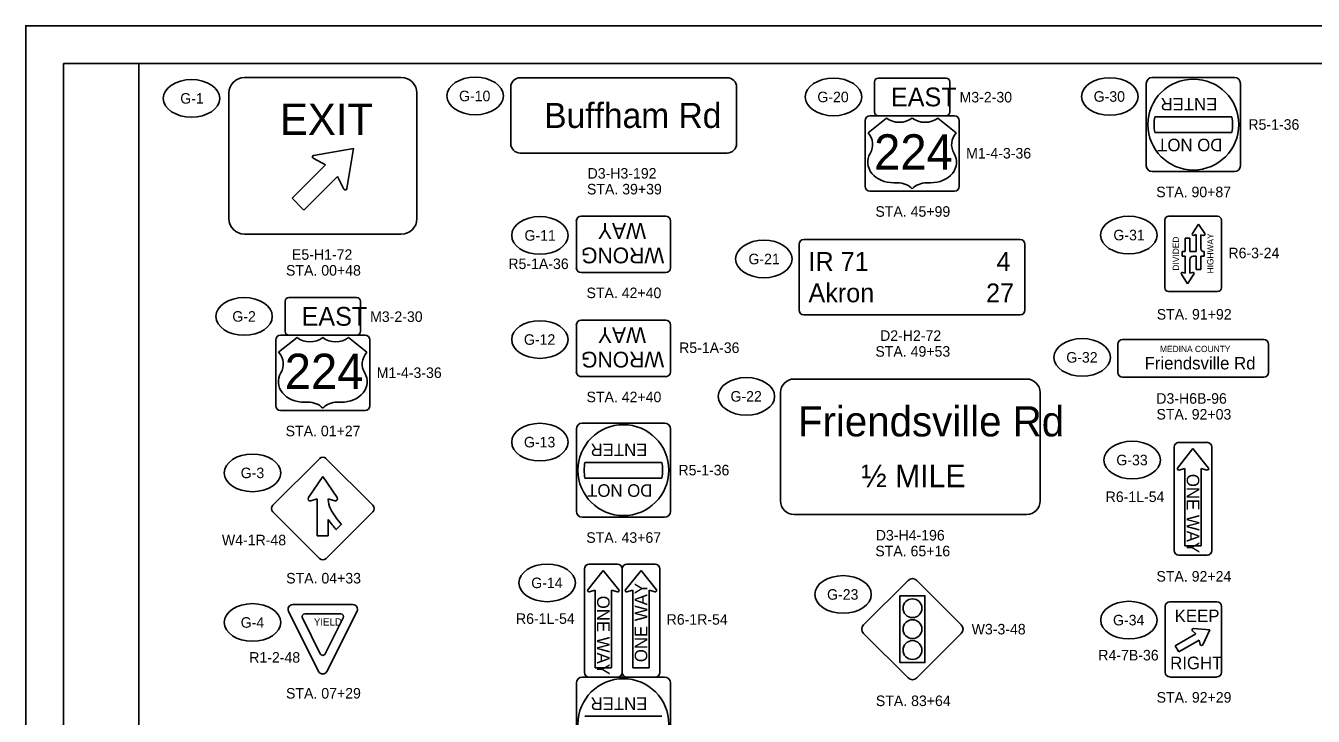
# Model space of a CAD drawing. Extents: x 0 to 34, y 0 to 22.
# Drawn here: x 0 to 17.1, y 12.83 to 22 of the extents above; entities that cross this region are included whole.
import ezdxf

# ---------------------------------------------------------------- set-up
doc = ezdxf.new("R2010")
doc.units = 0
for name, color, linetype in [('SH_Border', 7, 'Continuous'), ('SH_Cut_Line', 7, 'Continuous'), ('SH_Text', 7, 'Continuous'), ('SN_P_Signs', 7, 'Continuous')]:
    doc.layers.add(name, color=color, linetype=linetype)

msp = doc.modelspace()

# ---------------------------------------------------------------- linework, layer by layer
at = {"layer": 'SH_Border'}
for points in [[(0.5, 21.5), (1.5, 21.5), (1.5, 0.5), (0.5, 0.5)], [(1.5, 21.5), (33.5, 21.5), (33.5, 0.5), (1.5, 0.5)]]:
    msp.add_lwpolyline(points, close=True, dxfattribs=at)
at = {"layer": 'SH_Cut_Line'}
msp.add_lwpolyline([(0, 0), (34, 0), (34, 22), (0, 22)], close=True, dxfattribs=at)
at = {"layer": 'SH_Text'}
for points in [[(14.568, 17.83), (16.443, 17.83)], [(14.506, 17.393), (14.506, 17.768)], [(16.506, 17.768), (16.506, 17.393)], [(16.443, 17.33), (14.568, 17.33)]]:
    msp.add_lwpolyline(points, dxfattribs=at)
for centre, start, end in [((14.568, 17.768), 90, 180), ((16.443, 17.768), 0, 90), ((14.568, 17.393), 180, 270), ((16.443, 17.393), 270, 0)]:
    msp.add_arc(centre, 0.0625, start, end, dxfattribs=at)
for centre in [(2.201, 21.035), (5.969, 21.067), (10.728, 21.054), (14.399, 21.06), (6.829, 19.214), (14.651, 19.219), (9.804, 18.901), (2.9, 18.138), (6.829, 17.831), (14.032, 17.594), (9.571, 17.076), (6.829, 16.468), (14.696, 16.23), (3.011, 16.059), (6.925, 14.598), (10.855, 14.444), (3.011, 14.072), (14.653, 14.103)]:
    msp.add_ellipse(centre, major_axis=(0.375, 0), ratio=0.666667, dxfattribs=at)
at = {"layer": 'SN_P_Signs'}
for p, q in [((11.273, 20.854), (11.273, 21.254)), ((11.323, 21.304), (12.223, 21.304)), ((12.273, 21.254), (12.273, 20.854)), ((11.431, 20.773), (11.187, 20.577)), ((12.223, 20.804), (11.323, 20.804)), ((12.359, 20.577), (12.115, 20.773)), ((14.998, 20.791), (16.018, 20.791)), ((16.018, 20.583), (14.998, 20.583)), ((3.823, 20.278), (4.355, 20.368)), ((3.982, 20.152), (3.817, 20.239)), ((3.538, 19.708), (3.982, 20.152)), ((4.139, 19.995), (3.695, 19.55)), ((4.226, 19.83), (4.139, 19.995)), ((11.529, 19.913), (11.578, 19.913)), ((11.969, 19.913), (12.017, 19.913)), ((3.695, 19.55), (3.538, 19.708)), ((4.226, 19.83), (4.226, 19.83)), ((15.13, 18.518), (15.13, 19.418)), ((15.18, 19.468), (15.83, 19.468)), ((15.577, 19.364), (15.495, 19.238)), ((15.66, 19.238), (15.577, 19.364)), ((15.88, 19.418), (15.88, 18.518)), ((15.463, 19.176), (15.4, 19.176)), ((15.4, 19.176), (15.4, 18.999)), ((15.463, 18.999), (15.463, 19.176)), ((15.512, 19.215), (15.546, 19.225)), ((15.546, 19.225), (15.546, 18.999)), ((15.609, 19.041), (15.609, 19.224)), ((15.609, 19.224), (15.643, 19.215)), ((15.4, 18.999), (15.359, 18.999)), ((15.359, 18.999), (15.359, 18.937)), ((15.546, 18.999), (15.463, 18.999)), ((15.65, 18.937), (15.65, 18.999)), ((15.65, 18.999), (15.65, 18.999)), ((15.359, 18.937), (15.4, 18.937)), ((15.4, 18.937), (15.4, 18.711)), ((15.463, 18.711), (15.463, 18.895)), ((15.504, 18.937), (15.546, 18.937)), ((15.546, 18.937), (15.546, 18.76)), ((15.609, 18.76), (15.609, 18.937)), ((15.609, 18.937), (15.65, 18.937)), ((15.349, 18.698), (15.431, 18.572)), ((15.349, 18.698), (15.349, 18.698)), ((15.4, 18.711), (15.366, 18.72)), ((15.431, 18.572), (15.514, 18.698)), ((15.497, 18.72), (15.463, 18.711)), ((15.546, 18.76), (15.609, 18.76)), ((3.445, 17.939), (3.445, 18.339)), ((3.495, 18.389), (4.395, 18.389)), ((4.445, 18.339), (4.445, 17.939)), ((15.83, 18.468), (15.18, 18.468)), ((3.603, 17.857), (3.359, 17.662)), ((4.395, 17.889), (3.495, 17.889)), ((4.531, 17.662), (4.287, 17.857)), ((3.701, 16.998), (3.749, 16.998)), ((4.14, 16.998), (4.189, 16.998)), ((15.503, 16.382), (15.298, 16.122)), ((15.709, 16.122), (15.503, 16.382)), ((7.427, 16.199), (8.448, 16.199)), ((15.314, 16.097), (15.394, 16.118)), ((15.394, 16.118), (15.394, 15.09)), ((15.613, 15.09), (15.613, 16.118)), ((15.613, 16.118), (15.693, 16.097)), ((3.754, 15.732), (3.945, 16.012)), ((3.945, 16.012), (4.135, 15.732)), ((8.448, 15.991), (7.427, 15.991)), ((3.872, 15.715), (3.787, 15.688)), ((3.872, 15.221), (3.872, 15.715)), ((4.103, 15.688), (4.018, 15.715)), ((4.018, 15.715), (4.018, 15.705)), ((4.018, 15.44), (4.018, 15.221)), ((4.018, 15.221), (3.872, 15.221)), ((4.195, 15.376), (4.125, 15.306)), ((15.394, 15.09), (15.613, 15.09)), ((7.671, 14.763), (7.466, 14.504)), ((7.877, 14.504), (7.671, 14.763)), ((7.966, 14.504), (8.172, 14.763)), ((8.172, 14.763), (8.377, 14.504)), ((7.482, 14.479), (7.562, 14.499)), ((7.562, 14.499), (7.562, 13.471)), ((7.781, 13.471), (7.781, 14.499)), ((7.781, 14.499), (7.861, 14.479)), ((8.062, 14.499), (7.982, 14.479)), ((8.062, 13.471), (8.062, 14.499)), ((8.36, 14.479), (8.281, 14.499)), ((8.281, 14.499), (8.281, 13.471)), ((3.889, 13.422), (3.49, 14.22)), ((3.546, 14.31), (4.344, 14.31)), ((3.556, 14.31), (3.556, 14.31)), ((4.025, 14.31), (4.024, 14.31)), ((3.912, 13.655), (3.674, 14.132)), ((4.183, 14.185), (3.706, 14.185)), ((15.268, 13.763), (15.54, 13.919)), ((15.54, 13.919), (15.495, 13.96)), ((15.509, 13.991), (15.725, 13.972)), ((15.725, 13.972), (15.634, 13.776)), ((15.315, 13.682), (15.268, 13.763)), ((15.587, 13.838), (15.315, 13.682)), ((15.599, 13.78), (15.587, 13.838)), ((7.562, 13.471), (7.781, 13.471)), ((8.281, 13.471), (8.062, 13.471)), ((7.427, 12.826), (8.448, 12.826))]:
    msp.add_line(p, q, dxfattribs=at)
for points in [[(2.905, 21.313), (4.988, 21.313)], [(9.317, 21.309), (6.567, 21.309)], [(14.883, 21.234), (14.883, 20.14)], [(16.055, 21.312), (14.961, 21.312)], [(16.133, 20.14), (16.133, 21.234)], [(2.696, 19.438), (2.696, 21.105)], [(5.196, 21.105), (5.196, 19.438)], [(6.442, 21.184), (6.442, 20.434)], [(9.442, 20.434), (9.442, 21.184)], [(11.148, 20.741), (11.148, 19.866)], [(12.336, 20.804), (11.211, 20.804)], [(12.398, 19.866), (12.398, 20.741)], [(4.355, 20.368), (4.355, 20.368), (4.265, 19.836)], [(6.567, 20.309), (9.317, 20.309)], [(14.961, 20.062), (16.055, 20.062)], [(11.211, 19.804), (12.336, 19.804)], [(7.313, 19.408), (7.313, 18.783)], [(8.5, 19.471), (7.375, 19.471)], [(8.563, 18.783), (8.563, 19.408)], [(4.988, 19.23), (2.905, 19.23)], [(13.208, 19.16), (10.333, 19.16)], [(10.271, 19.097), (10.271, 18.222)], [(13.271, 18.222), (13.271, 19.097)], [(7.375, 18.721), (8.5, 18.721)], [(10.333, 18.16), (13.208, 18.16)], [(7.313, 18.025), (7.313, 17.4)], [(8.5, 18.088), (7.375, 18.088)], [(8.563, 17.4), (8.563, 18.025)], [(3.32, 17.826), (3.32, 16.951)], [(4.507, 17.889), (3.382, 17.889)], [(4.57, 16.951), (4.57, 17.826)], [(7.375, 17.338), (8.5, 17.338)], [(13.294, 17.306), (10.204, 17.306)], [(10.024, 17.126), (10.024, 15.687)], [(13.474, 15.687), (13.474, 17.126)], [(3.382, 16.889), (4.507, 16.889)], [(7.313, 16.642), (7.313, 15.548)], [(8.485, 16.72), (7.391, 16.72)], [(8.563, 15.548), (8.563, 16.642)], [(15.316, 16.465), (15.691, 16.465)], [(3.901, 16.248), (3.282, 15.629)], [(4.608, 15.629), (3.989, 16.248)], [(15.253, 15.028), (15.253, 16.403)], [(15.753, 16.403), (15.753, 15.028)], [(3.282, 15.541), (3.901, 14.922)], [(3.989, 14.922), (4.608, 15.541)], [(7.391, 15.47), (8.485, 15.47)], [(10.204, 15.507), (13.294, 15.507)], [(15.691, 14.965), (15.316, 14.965)], [(7.421, 13.409), (7.421, 14.784)], [(7.484, 14.846), (7.859, 14.846)], [(7.921, 14.784), (7.921, 13.409)], [(7.921, 14.784), (7.921, 13.409)], [(8.359, 14.846), (7.984, 14.846)], [(8.421, 13.409), (8.421, 14.784)], [(11.718, 14.631), (11.129, 14.042)], [(12.425, 14.042), (11.836, 14.631)], [(11.943, 13.538), (11.943, 14.427), (11.61, 14.427), (11.61, 13.538), (11.943, 13.538)], [(11.61, 13.538), (11.943, 13.538), (11.943, 14.427), (11.61, 14.427), (11.61, 13.538)], [(4.4, 14.22), (4.001, 13.422)], [(15.133, 13.41), (15.133, 14.285)], [(15.196, 14.347), (15.821, 14.347)], [(15.883, 14.285), (15.883, 13.41)], [(4.216, 14.132), (3.978, 13.655)], [(11.129, 13.924), (11.718, 13.335)], [(11.836, 13.335), (12.425, 13.924)], [(8.485, 13.346), (7.391, 13.346)], [(7.859, 13.346), (7.484, 13.346)], [(7.984, 13.346), (8.359, 13.346)], [(15.821, 13.347), (15.196, 13.347)], [(7.313, 13.268), (7.313, 12.175)], [(8.563, 12.175), (8.563, 13.268)]]:
    msp.add_lwpolyline(points, dxfattribs=at)
for centre, radius in [((15.508, 20.687), 0.604), ((7.938, 16.095), 0.604), ((11.777, 14.261), 0.125), ((11.777, 13.983), 0.125), ((11.777, 13.705), 0.125), ((7.938, 12.721), 0.604)]:
    msp.add_circle(centre, radius, dxfattribs=at)
for centre, radius, start, end in [((2.905, 21.105), 0.208, 90, 180), ((4.988, 21.105), 0.208, 0, 90), ((6.567, 21.184), 0.125, 90, 180), ((9.317, 21.184), 0.125, 0, 90), ((11.323, 21.254), 0.05, 90, 180), ((12.223, 21.254), 0.05, 0, 90), ((14.961, 21.234), 0.0781, 90, 180), ((16.055, 21.234), 0.0781, 0, 90), ((11.211, 20.741), 0.0625, 90, 180), ((11.323, 20.854), 0.05, 180, 270), ((12.223, 20.854), 0.05, 270, 0), ((12.336, 20.741), 0.0625, 0, 90), ((15.508, 20.687), 0.521, 168.463, 191.537), ((15.508, 20.687), 0.521, 348.463, 11.537), ((6.567, 20.434), 0.125, 180, 270), ((9.317, 20.434), 0.125, 270, 0), ((3.827, 20.257), 0.0208, 99.6076, 242.1805), ((14.961, 20.14), 0.0781, 180, 270), ((16.055, 20.14), 0.0781, 270, 360), ((11.211, 19.866), 0.0625, 180, 270), ((12.336, 19.866), 0.0625, 270, 0), ((4.244, 19.84), 0.0208, 207.8195, 350.3924), ((2.905, 19.438), 0.208, 180, 270), ((4.988, 19.438), 0.208, 270, 0), ((7.375, 19.408), 0.0625, 90, 180), ((8.5, 19.408), 0.0625, 0, 90), ((15.18, 19.418), 0.05, 90, 180), ((15.83, 19.418), 0.05, 0, 90), ((10.333, 19.097), 0.0625, 90, 180), ((13.208, 19.097), 0.0625, 0, 90), ((15.508, 19.23), 0.0153, 146.7604, 285.627), ((15.647, 19.23), 0.0153, 254.373, 33.2396), ((15.65, 19.041), 0.0416, 180, 270), ((15.504, 18.895), 0.0416, 90, 180), ((7.375, 18.783), 0.0625, 180, 270), ((8.5, 18.783), 0.0625, 270, 360), ((15.362, 18.706), 0.0153, 74.373, 213.2396), ((15.502, 18.706), 0.0153, 326.7604, 105.627), ((15.18, 18.518), 0.05, 180, 270), ((15.83, 18.518), 0.05, 270, 360), ((3.495, 18.339), 0.05, 90, 180), ((4.395, 18.339), 0.05, 0, 90), ((10.333, 18.222), 0.0625, 180, 270), ((13.208, 18.222), 0.0625, 270, 0), ((7.375, 18.025), 0.0625, 90, 180), ((8.5, 18.025), 0.0625, 0, 90), ((3.382, 17.826), 0.0625, 90, 180), ((3.495, 17.939), 0.05, 180, 270), ((4.395, 17.939), 0.05, 270, 0), ((4.507, 17.826), 0.0625, 0, 90), ((7.375, 17.4), 0.0625, 180, 270), ((8.5, 17.4), 0.0625, 270, 360), ((10.204, 17.126), 0.18, 90, 180), ((13.294, 17.126), 0.18, 0, 90), ((3.382, 16.951), 0.0625, 180, 270), ((4.507, 16.951), 0.0625, 270, 0), ((7.391, 16.642), 0.0781, 90, 180), ((8.485, 16.642), 0.0781, 0, 90), ((15.316, 16.403), 0.0625, 90, 180), ((15.691, 16.403), 0.0625, 360, 90), ((3.945, 16.204), 0.0625, 45, 135), ((7.938, 16.095), 0.521, 168.463, 191.537), ((7.938, 16.095), 0.521, 348.463, 11.537), ((15.311, 16.113), 0.0157, 141.6275, 284.2432), ((15.697, 16.113), 0.0157, 255.7826, 38.342), ((3.326, 15.585), 0.0625, 135, 225), ((3.778, 15.715), 0.0287, 145.86, 287.8182), ((4.283, 15.705), 0.266, 180, 207.6427), ((4.869, 16.012), 0.927, 207.6427, 223.3789), ((4.111, 15.715), 0.0287, 252.1818, 34.14), ((4.564, 15.585), 0.0625, 315, 45), ((10.204, 15.687), 0.18, 180, 270), ((13.294, 15.687), 0.18, 270, 360), ((4.869, 16.012), 1.026, 213.9044, 223.5353), ((7.391, 15.548), 0.0781, 180, 270), ((8.485, 15.548), 0.0781, 270, 360), ((3.945, 14.967), 0.0625, 225, 315), ((15.316, 15.028), 0.0625, 180, 270), ((15.691, 15.028), 0.0625, 270, 360), ((7.484, 14.784), 0.0625, 90, 180), ((7.859, 14.784), 0.0625, 360, 90), ((7.984, 14.784), 0.0625, 90, 180), ((8.359, 14.784), 0.0625, 360, 90), ((11.777, 14.572), 0.0833, 45, 135), ((7.478, 14.494), 0.0157, 141.6275, 284.2432), ((7.865, 14.494), 0.0157, 255.7826, 38.342), ((7.978, 14.494), 0.0157, 141.658, 284.2174), ((8.364, 14.494), 0.0157, 255.7568, 38.3725), ((11.777, 14.261), 0.125, 0, 180), ((3.546, 14.247), 0.0625, 90, 206.5651), ((4.344, 14.247), 0.0625, 333.4349, 90), ((11.777, 14.261), 0.125, 180, 0), ((15.196, 14.285), 0.0625, 90, 180), ((15.821, 14.285), 0.0625, 0, 90), ((3.706, 14.148), 0.0367, 90, 206.5651), ((4.183, 14.148), 0.0367, 333.4349, 90), ((11.187, 13.983), 0.0833, 135, 225), ((11.777, 13.983), 0.125, 0, 180), ((12.366, 13.983), 0.0833, 315, 45), ((11.777, 13.983), 0.125, 180, 0), ((15.508, 13.973), 0.0182, 84.9208, 227.6378), ((11.777, 13.705), 0.125, 0, 180), ((11.777, 13.705), 0.125, 180, 0), ((15.617, 13.784), 0.0182, 192.3622, 335.0792), ((3.945, 13.671), 0.0367, 206.5651, 333.4349), ((3.945, 13.45), 0.0625, 206.5651, 333.4349), ((7.391, 13.268), 0.0781, 90, 180), ((7.484, 13.409), 0.0625, 180, 270), ((7.859, 13.409), 0.0625, 270, 360), ((7.984, 13.409), 0.0625, 180, 270), ((8.359, 13.409), 0.0625, 270, 360), ((8.485, 13.268), 0.0781, 0, 90), ((15.196, 13.41), 0.0625, 180, 270), ((15.821, 13.41), 0.0625, 270, 0), ((11.777, 13.394), 0.0833, 225, 315)]:
    msp.add_arc(centre, radius, start, end, dxfattribs=at)
for centre, major_axis, start_param, end_param in [((11.602, 20.912), (-0.244, 0), 0.795399, 2.346194), ((11.944, 20.912), (-0.244, 0), 0.795399, 2.346194), ((10.907, 20.421), (0.342, 0), 5.838949, 6.894067), ((12.639, 20.421), (-0.342, 0), 5.672304, 6.727422), ((11.525, 20.187), (0.342, 0), 2.702327, 4.723529), ((12.021, 20.187), (-0.342, 0), 1.559657, 3.580859), ((11.578, 19.718), (-0.244, 0), 3.785094, 4.712389), ((11.969, 19.718), (-0.244, 0), 4.712389, 5.639684), ((3.774, 17.997), (-0.244, 0), 0.795399, 2.346194), ((4.116, 17.997), (-0.244, 0), 0.795399, 2.346194), ((3.079, 17.505), (0.342, 0), 5.838949, 6.894067), ((4.811, 17.505), (-0.342, 0), 5.672304, 6.727422), ((3.697, 17.271), (0.342, 0), 2.702327, 4.723529), ((4.193, 17.271), (-0.342, 0), 1.559657, 3.580859), ((3.749, 16.803), (-0.244, 0), 3.785094, 4.712389), ((4.14, 16.803), (-0.244, 0), 4.712389, 5.639684)]:
    msp.add_ellipse(centre, major_axis=major_axis, ratio=0.8, start_param=start_param, end_param=end_param, dxfattribs=at)

# ---------------------------------------------------------------- texts
at = {"layer": 'SH_Text'}
for s, p in [('G-1', (2.052, 20.965)), ('G-10', (5.755, 20.997)), ('G-20', (10.514, 20.984)), ('M3-2-30', (12.403, 20.981)), ('G-30', (14.184, 20.99)), ('R5-1-36', (16.239, 20.618)), ('M1-4-3-36', (12.49, 20.236)), ('D3-H3-192', (7.462, 19.969)), ('STA. 39+39', (7.454, 19.759)), ('STA. 90+87', (15.015, 19.722)), ('STA. 45+99', (11.285, 19.462)), ('G-11', (6.624, 19.144)), ('G-31', (14.446, 19.149)), ('E5-H1-72', (3.536, 18.89)), ('R6-3-24', (15.974, 18.911)), ('STA. 00+48', (3.457, 18.68)), ('R5-1A-36', (6.41, 18.767)), ('G-21', (9.599, 18.831)), ('STA. 42+40', (7.448, 18.381)), ('G-2', (2.744, 18.068)), ('M3-2-30', (4.574, 18.065)), ('STA. 91+92', (15.022, 18.096)), ('G-12', (6.617, 17.761)), ('R5-1A-36', (8.678, 17.652)), ('D2-H2-72', (11.347, 17.813)), ('STA. 49+53', (11.285, 17.603)), ('G-32', (13.82, 17.524)), ('M1-4-3-36', (4.661, 17.32)), ('STA. 42+40', (7.448, 16.998)), ('G-22', (9.36, 17.006)), ('D3-H6B-96', (15.016, 16.978)), ('STA. 92+03', (15.018, 16.768)), ('STA. 01+27', (3.452, 16.546)), ('G-13', (6.617, 16.398)), ('G-33', (14.485, 16.16)), ('G-3', (2.855, 15.989)), ('R5-1-36', (8.669, 16.026)), ('R6-1L-54', (14.343, 15.672)), ('W4-1R-48', (2.605, 15.097)), ('STA. 43+67', (7.445, 15.13)), ('D3-H4-196', (11.29, 15.161)), ('STA. 65+16', (11.284, 14.951)), ('STA. 04+33', (3.459, 14.59)), ('STA. 92+24', (15.018, 14.615)), ('G-14', (6.714, 14.528)), ('G-23', (10.643, 14.374)), ('R6-1L-54', (6.511, 14.053)), ('G-4', (2.855, 14.002)), ('R6-1R-54', (8.512, 14.042)), ('W3-3-48', (12.563, 13.913)), ('G-34', (14.441, 14.033)), ('R4-7B-36', (14.246, 13.567)), ('R1-2-48', (2.968, 13.538)), ('STA. 07+29', (3.457, 13.061)), ('STA. 83+64', (11.291, 12.961)), ('STA. 92+29', (15.02, 13.007))]:
    msp.add_text(s, height=0.14, dxfattribs=at).set_placement(p)
at = {"layer": 'SN_P_Signs'}
for s, height, p in [('EAST', 0.25, (11.491, 20.929)), ('EXIT', 0.4167, (3.375, 20.549)), ('Buffham Rd', 0.3333, (6.886, 20.642)), ('224', 0.4688, (11.268, 20.089)), ('IR 71', 0.25, (10.396, 18.743)), ('4', 0.25, (12.894, 18.743)), ('Akron', 0.25, (10.396, 18.326)), ('27', 0.25, (12.755, 18.326)), ('EAST', 0.25, (3.663, 18.014)), ('224', 0.4688, (3.44, 17.174)), ('MEDINA COUNTY', 0.08333, (15.065, 17.664)), ('Friendsville Rd', 0.16667, (14.86, 17.434)), ('Friendsville Rd', 0.39984, (10.256, 16.544)), ('½ MILE', 0.3, (11.1, 15.869)), ('KEEP', 0.1667, (15.26, 14.076)), ('YIELD', 0.0962, (3.827, 14.031)), ('RIGHT', 0.1667, (15.2, 13.451))]:
    msp.add_text(s, height=height, dxfattribs=at).set_placement(p)
for s, height, rotation, p in [('ENTER', 0.1667, 180, (15.827, 21.041)), ('DO NOT', 0.1667, 180, (15.894, 20.499)), ('WAY', 0.2094, 180, (8.238, 19.378)), ('DIVIDED', 0.0833, 90, (15.317, 18.747)), ('HIGHWAY', 0.0833, 90, (15.775, 18.709)), ('WRONG', 0.2094, 180, (8.48, 19.053)), ('WAY', 0.2094, 180, (8.238, 17.994)), ('WRONG', 0.2094, 180, (8.48, 17.669)), ('ENTER', 0.1667, 180, (8.257, 16.449)), ('DO NOT', 0.1667, 180, (8.323, 15.908)), ('ONE WAY', 0.1667, 270, (15.42, 16.046)), ('ONE WAY', 0.1667, 90, (8.255, 13.544)), ('ONE WAY', 0.1667, 270, (7.588, 14.427)), ('ENTER', 0.1667, 180, (8.257, 13.076))]:
    msp.add_text(s, height=height, rotation=rotation, dxfattribs=at).set_placement(p)

doc.saveas('drawing.dxf')
